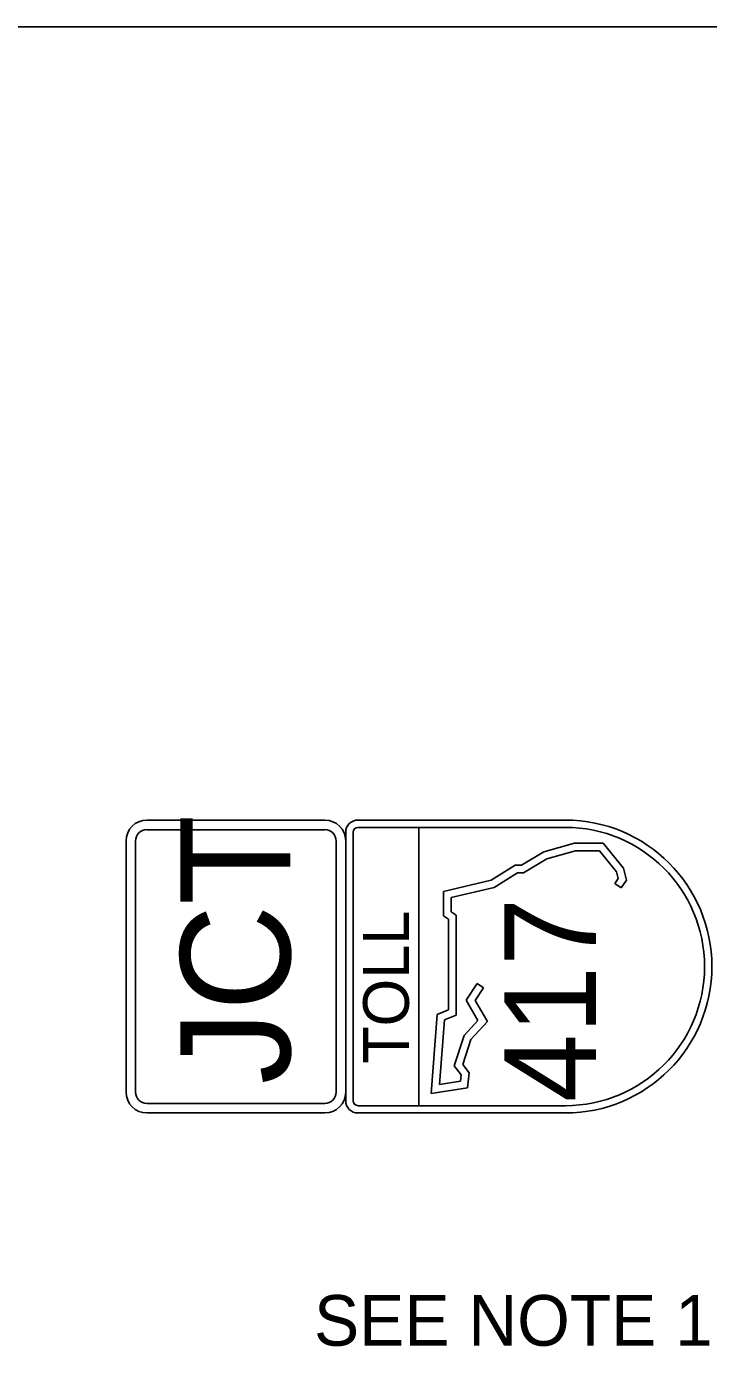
# Model space of a CAD drawing. Extents: x -830008.4 to -829992.7, y 1290284.1 to 1290294.4.
# Drawn here: x -829994.961 to -829994.019, y 1290292.375 to 1290294.228 of the extents above; entities that cross this region are included whole.
import ezdxf

# ---------------------------------------------------------------- set-up
doc = ezdxf.new("R2010")
doc.units = 0
for name, color, linetype in [('NonPlottingEle_dp', 7, 'Continuous'), ('SignPanel', 7, 'Continuous'), ('TextLabel', 7, 'Continuous')]:
    doc.layers.add(name, color=color, linetype=linetype)

msp = doc.modelspace()

# ---------------------------------------------------------------- linework, layer by layer
at = {"layer": 'NonPlottingEle_dp'}
msp.add_lwpolyline([(-830007.4742, 1290294.228), (-829992.7742, 1290294.228), (-829992.7742, 1290285.328), (-830007.4742, 1290285.328)], close=True, dxfattribs=at)
at = {"layer": 'SignPanel'}
for p, q in [((-829994.2465, 1290293.0875), (-829994.2041, 1290293.0991)), ((-829994.2041, 1290293.0991), (-829994.1645, 1290293.0991)), ((-829994.1645, 1290293.0991), (-829994.1362, 1290293.0645)), ((-829994.2775, 1290293.0687), (-829994.2465, 1290293.0875)), ((-829994.2027, 1290293.0885), (-829994.2423, 1290293.0777)), ((-829994.1695, 1290293.0885), (-829994.2027, 1290293.0885)), ((-829994.1459, 1290293.0597), (-829994.1695, 1290293.0885)), ((-829994.3193, 1290293.0479), (-829994.2859, 1290293.0687)), ((-829994.2859, 1290293.0687), (-829994.2775, 1290293.0687)), ((-829994.2423, 1290293.0777), (-829994.2745, 1290293.0581)), ((-829994.1436, 1290293.0502), (-829994.1459, 1290293.0597)), ((-829994.1362, 1290293.0645), (-829994.1322, 1290293.0481)), ((-829994.3851, 1290293.0326), (-829994.3193, 1290293.0479)), ((-829994.2829, 1290293.0581), (-829994.3152, 1290293.038)), ((-829994.2745, 1290293.0581), (-829994.2829, 1290293.0581)), ((-829994.1481, 1290293.0437), (-829994.1436, 1290293.0502)), ((-829994.1395, 1290293.0377), (-829994.1481, 1290293.0437)), ((-829994.1322, 1290293.0481), (-829994.1395, 1290293.0377)), ((-829994.3851, 1290292.9988), (-829994.3851, 1290293.0326)), ((-829994.3152, 1290293.038), (-829994.3745, 1290293.0242)), ((-829994.3745, 1290293.0242), (-829994.3745, 1290293.0044)), ((-829994.3745, 1290293.0044), (-829994.3675, 1290292.9997)), ((-829994.3781, 1290292.9941), (-829994.3851, 1290292.9988)), ((-829994.3781, 1290292.8687), (-829994.3781, 1290292.9941)), ((-829994.3675, 1290292.9997), (-829994.3675, 1290292.8614)), ((-829994.354, 1290292.8822), (-829994.3385, 1290292.9051)), ((-829994.3298, 1290292.8992), (-829994.3415, 1290292.8818)), ((-829994.3385, 1290292.9051), (-829994.3298, 1290292.8992)), ((-829994.3375, 1290292.8542), (-829994.354, 1290292.8822)), ((-829994.3415, 1290292.8818), (-829994.3244, 1290292.8527)), ((-829994.4022, 1290292.7532), (-829994.3938, 1290292.8625)), ((-829994.3938, 1290292.8625), (-829994.3781, 1290292.8687)), ((-829994.3675, 1290292.8614), (-829994.3838, 1290292.8551)), ((-829994.3838, 1290292.8551), (-829994.3907, 1290292.7657)), ((-829994.3567, 1290292.8335), (-829994.3375, 1290292.8542)), ((-829994.3244, 1290292.8527), (-829994.3474, 1290292.828)), ((-829994.3704, 1290292.7913), (-829994.3567, 1290292.8335)), ((-829994.3474, 1290292.828), (-829994.3586, 1290292.7934)), ((-829994.3606, 1290292.7788), (-829994.3704, 1290292.7913)), ((-829994.3586, 1290292.7934), (-829994.3496, 1290292.7819)), ((-829994.3496, 1290292.7819), (-829994.3522, 1290292.761)), ((-829994.3907, 1290292.7657), (-829994.3617, 1290292.7702)), ((-829994.3617, 1290292.7702), (-829994.3606, 1290292.7788)), ((-829994.3522, 1290292.761), (-829994.4022, 1290292.7532))]:
    msp.add_line(p, q, dxfattribs=at)
for points in [[(-829994.7952, 1290293.1312), (-829994.5493, 1290293.1312)], [(-829994.7952, 1290293.1179), (-829994.5493, 1290293.1179)], [(-829994.5035, 1290293.1312), (-829994.2166, 1290293.1312)], [(-829994.5035, 1290293.1211), (-829994.2166, 1290293.1211)], [(-829994.4191, 1290292.7363), (-829994.4191, 1290293.1211)], [(-829994.8241, 1290292.7551), (-829994.8241, 1290293.1023)], [(-829994.8109, 1290292.7551), (-829994.8109, 1290293.1023)], [(-829994.5336, 1290293.1023), (-829994.5336, 1290292.7551)], [(-829994.5204, 1290292.7431), (-829994.5204, 1290293.1143)], [(-829994.5204, 1290293.1023), (-829994.5204, 1290292.7551)], [(-829994.5102, 1290292.7431), (-829994.5102, 1290293.1143)], [(-829994.5493, 1290292.7394), (-829994.7952, 1290292.7394)], [(-829994.5493, 1290292.7262), (-829994.7952, 1290292.7262)], [(-829994.2166, 1290292.7363), (-829994.5035, 1290292.7363)], [(-829994.2166, 1290292.7262), (-829994.5035, 1290292.7262)]]:
    msp.add_lwpolyline(points, dxfattribs=at)
for centre, radius, start, end in [((-829994.7952, 1290293.1023), 0.0289, 90, 180), ((-829994.7952, 1290293.1023), 0.0157, 90.0544, 180), ((-829994.5493, 1290293.1023), 0.0289, 0, 90), ((-829994.5493, 1290293.1023), 0.0157, 0, 90), ((-829994.5035, 1290293.1143), 0.0169, 90, 180), ((-829994.5035, 1290293.1143), 0.00675, 90, 180), ((-829994.2166, 1290292.9287), 0.2025, 270, 90), ((-829994.2166, 1290292.9287), 0.1924, 270, 90), ((-829994.7952, 1290292.7551), 0.0289, 180, 270), ((-829994.7952, 1290292.7551), 0.0157, 180, 269.9456), ((-829994.5493, 1290292.7551), 0.0289, 270, 0), ((-829994.5493, 1290292.7551), 0.0157, 270, 0), ((-829994.5035, 1290292.7431), 0.0169, 180, 270), ((-829994.5035, 1290292.7431), 0.00675, 180, 270)]:
    msp.add_arc(centre, radius, start, end, dxfattribs=at)

# ---------------------------------------------------------------- texts
for s, height, p in [('JCT', 0.15188, (-829994.5971, 1290292.7658)), ('417', 0.12656, (-829994.1744, 1290292.7413)), ('TOLL', 0.06328, (-829994.433, 1290292.7942))]:
    msp.add_text(s, height=height, rotation=90, dxfattribs=at).set_placement(p)
at = {"layer": 'TextLabel'}
msp.add_text('SEE NOTE 1 AND 2', height=0.07, rotation=0.0044, dxfattribs=at).set_placement((-829994.5642, 1290292.4044))

doc.saveas('drawing.dxf')
